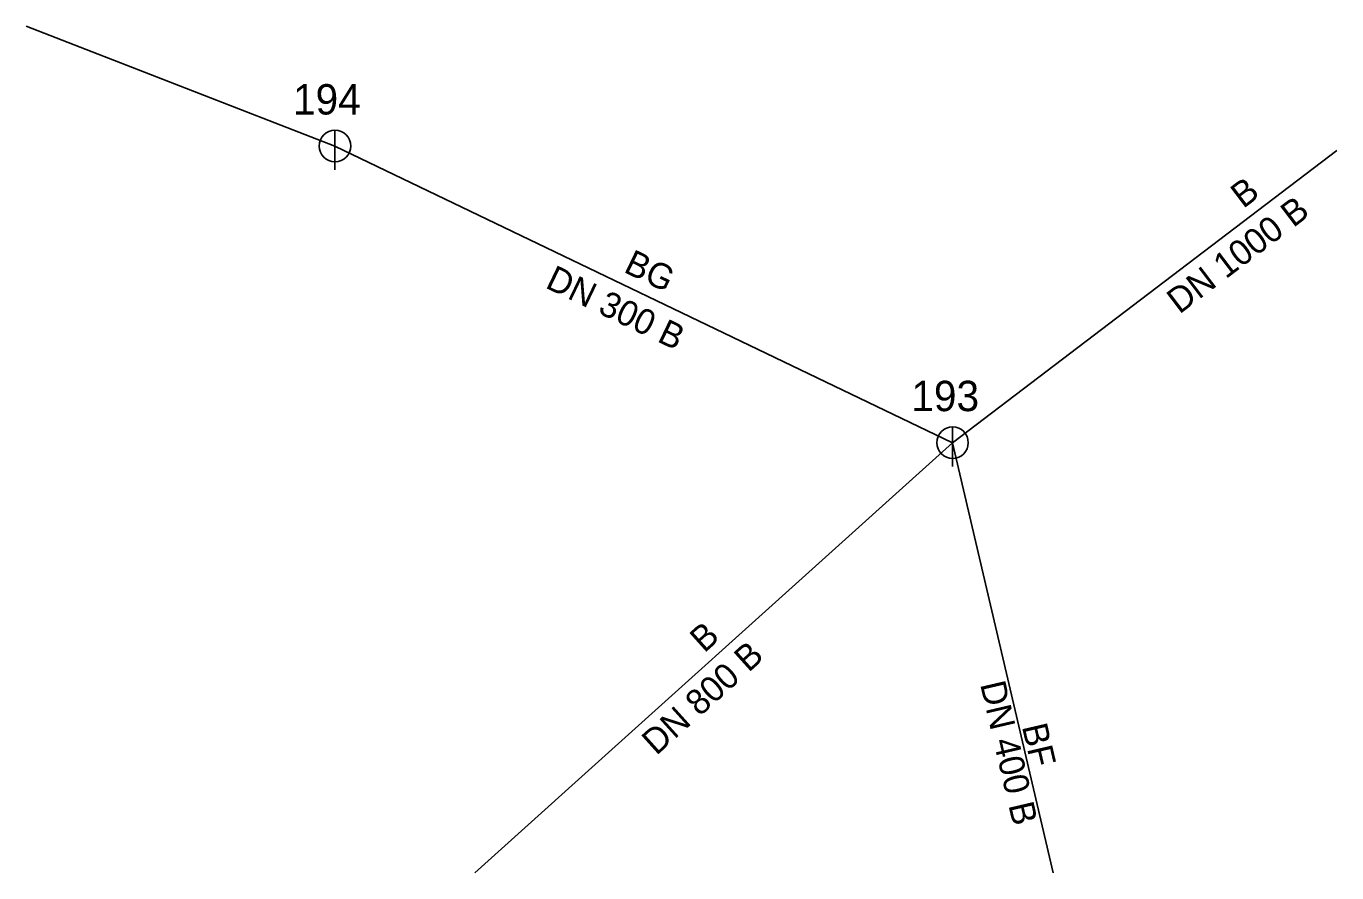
# Model space of a CAD drawing. Extents: x -468327.6 to -468244.4, y -1119298.8 to -1119245.1.
import ezdxf

# ---------------------------------------------------------------- set-up
doc = ezdxf.new("R2010")
doc.units = 0
for name, color, linetype in [('_stoka_jednotna_smvak_prevzato_z_dokumentace_', 7, 'Continuous'), ('Default', 7, 'Continuous'), ('MoLevel 119', 7, 'Continuous'), ('MoLevel 120', 7, 'Continuous'), ('MoLevel 68', 7, 'Continuous'), ('MoLevel 69', 7, 'Continuous')]:
    doc.layers.add(name, color=color, linetype=linetype)

# ---------------------------------------------------------------- blocks, each defined once
blk = doc.blocks.new('_sachta_kanal_prevzato_z_dokumentace_')
at = {"layer": 'Default'}
blk.add_line((0, 0.00005), (0, -0.000075), dxfattribs=at)
blk.add_circle((0, 0), 0.00005, dxfattribs=at)

msp = doc.modelspace()

# ---------------------------------------------------------------- linework, layer by layer
at = {"layer": '_stoka_jednotna_smvak_prevzato_z_dokumentace_'}
for p, q in [((-468327.551, -1119245.082), (-468307.97, -1119252.68)), ((-468307.97, -1119252.68), (-468268.8, -1119271.49)), ((-468268.8, -1119271.49), (-468244.429, -1119252.973)), ((-468299.095, -1119298.762), (-468268.8, -1119271.49)), ((-468262.424, -1119298.762), (-468268.8, -1119271.49))]:
    msp.add_line(p, q, dxfattribs=at)

# ---------------------------------------------------------------- block references
at = {"layer": 'MoLevel 119', "xscale": 20000, "yscale": 20000}
for p in [(-468307.97, -1119252.68), (-468268.799, -1119271.49)]:
    msp.add_blockref('_sachta_kanal_prevzato_z_dokumentace_', p, dxfattribs=at)

# ---------------------------------------------------------------- texts
at = {"layer": 'MoLevel 120'}
for s, p in [('194', (-468310.63, -1119250.68)), ('193', (-468271.412, -1119269.49))]:
    msp.add_text(s, height=1.9259, dxfattribs=at).set_placement(p)
at = {"layer": 'MoLevel 68'}
for s, rotation, p in [('DN 1000 B', 37.22795, (-468254.412, -1119263.374)), ('DN 300 B', 334.34901, (-468294.695, -1119261.635)), ('DN 800 B', 41.99324, (-468287.59, -1119291.364)), ('DN 400 B', 283.15912, (-468267.056, -1119286.8))]:
    msp.add_text(s, height=1.6049, rotation=rotation, dxfattribs=at).set_placement(p)
at = {"layer": 'MoLevel 69'}
for s, height, rotation, p in [('B', 1.605, 37.22795, (-468250.363, -1119256.681)), ('BG', 1.6049, 334.34901, (-468289.728, -1119260.64)), ('B', 1.605, 41.99324, (-468284.545, -1119284.864)), ('BF', 1.6049, 283.15912, (-468264.406, -1119289.486))]:
    msp.add_text(s, height=height, rotation=rotation, dxfattribs=at).set_placement(p)

doc.saveas('drawing.dxf')
